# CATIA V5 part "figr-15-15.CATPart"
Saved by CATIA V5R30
Part number: Part1
Bounding box of the stored display mesh (mm): x -75 to 75, y -66.397 to 33.603, z 0 to 1
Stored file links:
  D:\PROJECTS\CATIA V56R 2020\Resources\Parts File\c15_catia_v5_6r2020_prt\figr-15-15.CATPart
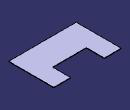
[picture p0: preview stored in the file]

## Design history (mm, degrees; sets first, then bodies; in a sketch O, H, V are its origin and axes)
SheetMetalParameters1: Thickness 1, BendRadius 1, KFactor 0.325257 {= log(min(100,max(20*SheetMetalParameters1.BendRadius,SheetMetalParameters1.Thickness)/SheetMetalParameters1.Thickness))/log(100)/2}, ReliefRadialLength 1, ReliefAxialLength 2, MinimumBendRadius 0
Body1 (main body)
  Sketch1 on xy-plane, origin (0, 0, 0), H (1, 0, 0), V (0, 1, 0)
    line L1 (-37.5, 33.6029) -> (-37.5, -6.3971)
    line L2 (-37.5, -6.3971) -> (37.5, -6.3971)
    line L3 (37.5, -6.3971) -> (37.5, 33.6029)
    line L4 (37.5, 33.6029) -> (75, 33.6029)
    line L5 (75, 33.6029) -> (75, -66.3971)
    line L6 (75, -66.3971) -> (-75, -66.3971)
    line L7 (-75, -66.3971) -> (-75, 33.6029)
    point P8 (-75, 33.6029)
    line L8 (-75, 33.6029) -> (-37.5, 33.6029)
    length L7 = 100
    length L1 = 40
    length L6 = 150
    distance L1 L3 = 75
    vertical: L1 V, L3 V, L5 V, L7 V
    horizontal: L2 H, L4 H, L6 H, L8 H
    coincidence: P8 L4
    symmetry: L7 L5 V, L1 L3 V
  Wall1: Thickness 1, Profile Sketch1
